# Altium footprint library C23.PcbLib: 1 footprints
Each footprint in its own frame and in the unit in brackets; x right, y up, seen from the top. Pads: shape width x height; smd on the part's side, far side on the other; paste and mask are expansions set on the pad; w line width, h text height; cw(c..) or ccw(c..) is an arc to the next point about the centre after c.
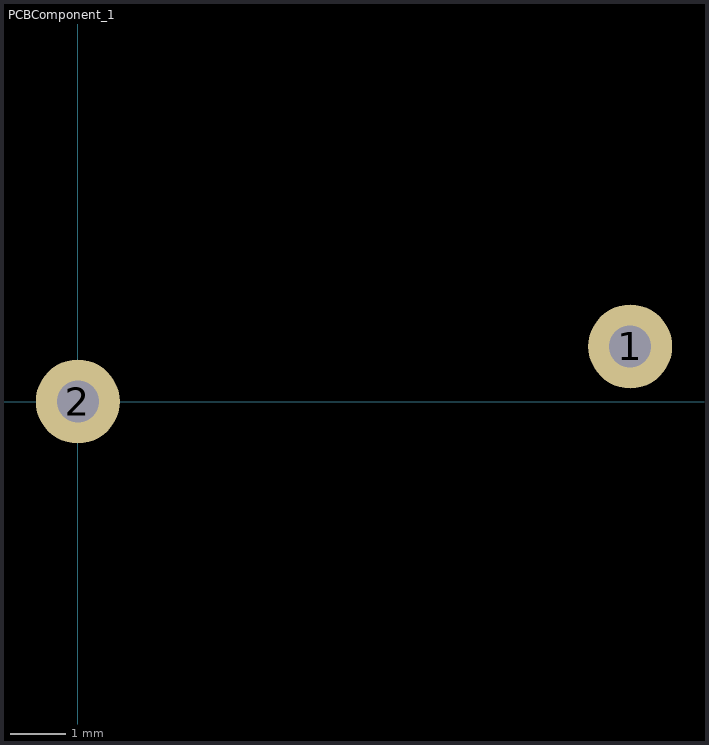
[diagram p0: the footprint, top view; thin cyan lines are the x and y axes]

## PCBComponent_1 [mil]
pads (2):
  round 60 hole 30: 1(394.69,39.37) 2(0,0)
M5 Assembly Top:
  text ".Designator" at -78.74,-27.56 h72.83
